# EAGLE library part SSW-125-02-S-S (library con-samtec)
THROUGH-HOLE .025" SQ POST SOCKET Source: Samtec SSW.pdf
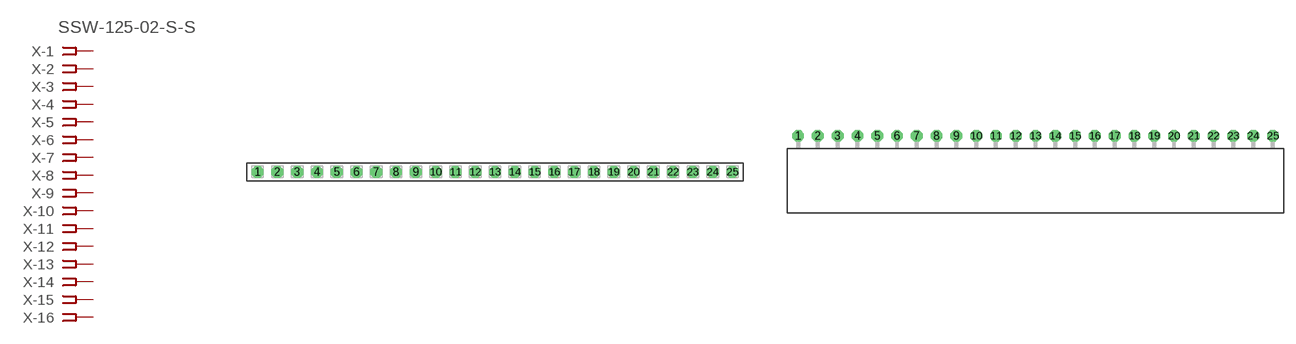
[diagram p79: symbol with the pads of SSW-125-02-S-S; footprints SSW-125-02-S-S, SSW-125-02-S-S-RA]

Designator prefix X; gates -1=FPINV -2=FPIN -3=FPIN -4=FPIN -5=FPIN -6=FPIN -7=FPIN -8=FPIN -9=FPIN -10=FPIN -11=FPIN -12=FPIN -13=FPIN -14=FPIN -15=FPIN -16=FPIN -17=FPIN -18=FPIN -19=FPIN -20=FPIN -21=FPIN -22=FPIN -23=FPIN -24=FPIN -25=FPIN

## SSW-125-02-S-S (MPN: SSW-125-02-S-S; OC_FARNELL: unknown; OC_NEWARK: 11P9725)  [SSW-125-02-S-S]
1  -1:1  pas
2  -2:1  pas
3  -3:1  pas
4  -4:1  pas
5  -5:1  pas
6  -6:1  pas
7  -7:1  pas
8  -8:1  pas
9  -9:1  pas
10  -10:1  pas
11  -11:1  pas
12  -12:1  pas
13  -13:1  pas
14  -14:1  pas
15  -15:1  pas
16  -16:1  pas
17  -17:1  pas
18  -18:1  pas
19  -19:1  pas
20  -20:1  pas
21  -21:1  pas
22  -22:1  pas
23  -23:1  pas
24  -24:1  pas
25  -25:1  pas

## SSW-125-02-S-S-RA (MPN: SSW-125-02-S-S-RA; OC_FARNELL: unknown; OC_NEWARK: 11P9726)  [SSW-125-02-S-S-RA]
Pads as for SSW-125-02-S-S

## Footprint SSW-125-02-S-S (pad centres in mm)
THROUGH-HOLE .025" SQ POST SOCKET Source: Samtec SSW.pdf
drill 1 pad 1.5 octagon: 1 -30.48,0; 2 -27.94,0; 3 -25.4,0; 4 -22.86,0; 5 -20.32,0; 6 -17.78,0; 7 -15.24,0; 8 -12.7,0; 9 -10.16,0; 10 -7.62,0; 11 -5.08,0; 12 -2.54,0; 13 0,0; 14 2.54,0; 15 5.08,0; 16 7.62,0; 17 10.16,0; 18 12.7,0; 19 15.24,0; 20 17.78,0; 21 20.32,0; 22 22.86,0; 23 25.4,0; 24 27.94,0; 25 30.48,0

## Footprint SSW-125-02-S-S-RA (pad centres in mm)
THROUGH-HOLE .025" SQ POST SOCKET Source: Samtec SSW.pdf
drill 1 pad 1.5 octagon: 1 -30.48,1.524; 2 -27.94,1.524; 3 -25.4,1.524; 4 -22.86,1.524; 5 -20.32,1.524; 6 -17.78,1.524; 7 -15.24,1.524; 8 -12.7,1.524; 9 -10.16,1.524; 10 -7.62,1.524; 11 -5.08,1.524; 12 -2.54,1.524; 13 0,1.524; 14 2.54,1.524; 15 5.08,1.524; 16 7.62,1.524; 17 10.16,1.524; 18 12.7,1.524; 19 15.24,1.524; 20 17.78,1.524; 21 20.32,1.524; 22 22.86,1.524; 23 25.4,1.524; 24 27.94,1.524; 25 30.48,1.524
